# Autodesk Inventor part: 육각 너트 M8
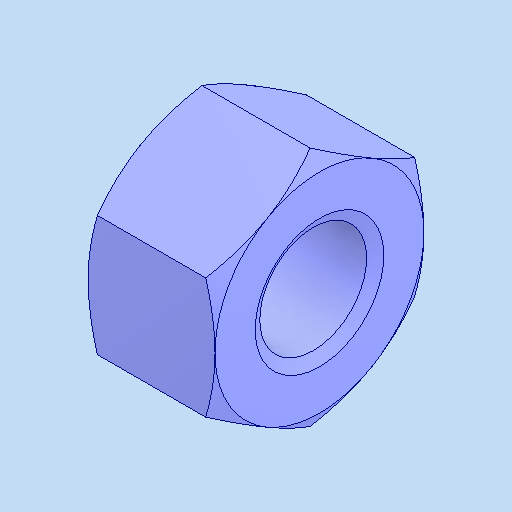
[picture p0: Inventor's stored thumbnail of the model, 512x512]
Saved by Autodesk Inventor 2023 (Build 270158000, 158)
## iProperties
Created: 2024-11
Part Number: 육각 너트 M8
Material: 강철, 연강
Description: 6각 너트 및 6각 가는 너트
Document SubType Name: Modeling
Designer: asung
Density: 7.85 g/cm^3
Appearance: 기본값
Author: jhkim
Sending System: Autodesk Inventor 2025
Preprocessor: ST-DEVELOPER v20
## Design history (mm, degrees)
feature "Solid1"
node "솔리드1"
